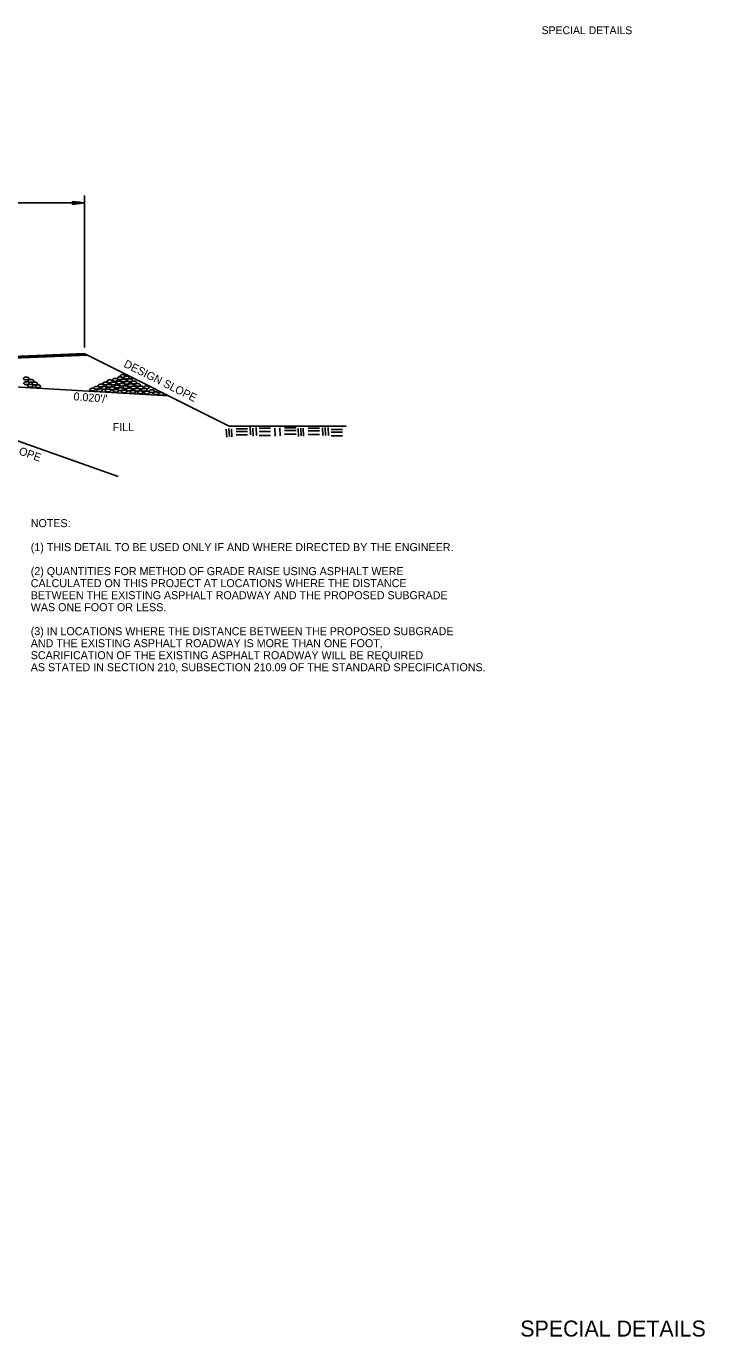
# Model space of a CAD drawing. Extents: x 836 to 5683, y -463 to 1545.
# Drawn here: x 5174 to 5683, y 35 to 1017 of the extents above; entities that cross this region are included whole.
import ezdxf

# ---------------------------------------------------------------- set-up
doc = ezdxf.new("R2010")
doc.units = 0
for name, color, linetype in [('R_Border', 7, 'Continuous'), ('R_Border Prem', 7, 'Continuous'), ('R_Grid', 7, 'Continuous'), ('R_No Plot', 7, 'Continuous')]:
    doc.layers.add(name, color=color, linetype=linetype)

msp = doc.modelspace()

# ---------------------------------------------------------------- linework, layer by layer
at = {"layer": 'R_Grid'}
for p, q in [((4657.04, 884.96), (5217.98, 884.96)), ((5209.15, 886.1), (5217.98, 884.96)), ((5209.15, 883.81), (5209.15, 886.1)), ((5209.15, 885.87), (5210.88, 885.88)), ((5209.15, 885.64), (5212.67, 885.65)), ((5209.15, 885.42), (5214.45, 885.41)), ((5209.15, 885.18), (5216.18, 885.18)), ((5217.98, 884.96), (5209.15, 884.96)), ((5209.15, 883.81), (5217.98, 884.96)), ((5209.15, 884.73), (5216.18, 884.73)), ((5209.15, 884.5), (5214.45, 884.51)), ((5209.16, 884.27), (5212.67, 884.27)), ((5217.98, 776.58), (5217.98, 890.46)), ((5209.15, 884.04), (5210.89, 884.05))]:
    msp.add_line(p, q, dxfattribs=at)
at = {"layer": 'R_No Plot'}
for p, q in [((4654.18, 748.2), (5220.52, 770.79)), ((4654.91, 748.58), (5219.89, 771.11)), ((4655.64, 748.93), (5219.26, 771.42)), ((4656.39, 749.31), (5218.6, 771.74)), ((4657.04, 749.63), (5218, 772.04)), ((5326.58, 717.76), (5217.91, 772.08)), ((5146.72, 748.27), (5281.29, 740.39)), ((5091.21, 733.94), (5243.32, 679.81)), ((5414.15, 717.76), (5326.58, 717.76)), ((5342.3, 717.13), (5342.61, 711.22)), ((5324.36, 715.43), (5324.69, 709.5)), ((5326.39, 715.82), (5326.73, 709.9)), ((5328.17, 715.63), (5328.49, 709.71)), ((5340.36, 715.63), (5331.79, 715.63)), ((5340.36, 713.66), (5331.79, 713.66)), ((5340.36, 711.02), (5331.79, 711.02)), ((5344.3, 716.13), (5344.62, 710.21)), ((5346.83, 716.65), (5347.15, 710.71)), ((5357.53, 716.14), (5348.93, 716.14)), ((5357.53, 713.6), (5348.93, 713.6)), ((5357.53, 710.58), (5348.93, 710.58)), ((5360.7, 716.07), (5361.05, 710.14)), ((5364.51, 716.28), (5364.84, 710.36)), ((5376.7, 716.28), (5368.14, 716.28)), ((5376.7, 714.3), (5368.14, 714.3)), ((5376.7, 711.66), (5368.14, 711.66)), ((5378.24, 715.81), (5378.57, 709.89)), ((5380.29, 716.23), (5380.6, 710.3)), ((5382.05, 716.02), (5382.38, 710.08)), ((5394.24, 716.02), (5385.68, 716.02)), ((5394.24, 714.06), (5385.68, 714.06)), ((5394.24, 711.42), (5385.68, 711.42)), ((5396.41, 716.44), (5396.74, 710.52)), ((5398.53, 716.67), (5398.86, 710.75)), ((5400.78, 716.67), (5401.11, 710.75)), ((5411.53, 715.12), (5402.96, 715.12)), ((5411.53, 713.17), (5402.96, 713.17)), ((5411.53, 710.51), (5402.96, 710.51))]:
    msp.add_line(p, q, dxfattribs=at)
for points in [[(5174.26, 752.35), (5173.52, 752.44), (5172.67, 752.66), (5172.25, 753.09), (5172.18, 753.31), (5172.39, 753.77), (5172.64, 753.98), (5173.11, 754.27), (5173.81, 754.41), (5174.16, 754.41), (5174.71, 754.43), (5175.31, 754.35), (5175.79, 754.08), (5176.23, 753.75), (5176.29, 753.47), (5176.18, 753.06), (5175.82, 752.77), (5175.52, 752.63), (5175.02, 752.48), (5174.71, 752.4), (5174.26, 752.35)], [(5174.56, 748.78), (5173.81, 748.85), (5172.97, 749.1), (5172.55, 749.51), (5172.47, 749.76), (5172.72, 750.2), (5172.92, 750.41), (5173.42, 750.65), (5174.11, 750.84), (5174.47, 750.84), (5175.03, 750.79), (5175.62, 750.75), (5176.11, 750.57), (5176.54, 750.16), (5176.61, 749.92), (5176.47, 749.48), (5176.15, 749.24), (5175.8, 749.08), (5175.31, 748.88), (5175.03, 748.79), (5174.56, 748.78)], [(5177.48, 746.82), (5176.72, 746.9), (5175.85, 747.14), (5175.43, 747.55), (5175.35, 747.81), (5175.57, 748.24), (5175.81, 748.45), (5176.31, 748.72), (5177.01, 748.88), (5177.39, 748.88), (5177.93, 748.84), (5178.53, 748.81), (5178.99, 748.61), (5179.43, 748.21), (5179.48, 747.95), (5179.35, 747.53), (5179.02, 747.28), (5178.69, 747.13), (5178.22, 746.94), (5177.93, 746.83), (5177.48, 746.82)], [(5177.95, 750.6), (5177.21, 750.65), (5176.35, 750.9), (5175.92, 751.3), (5175.86, 751.57), (5176.12, 751.99), (5176.3, 752.21), (5176.82, 752.47), (5177.5, 752.65), (5177.85, 752.65), (5178.41, 752.61), (5179.02, 752.57), (5179.48, 752.36), (5179.93, 751.97), (5180, 751.71), (5179.86, 751.28), (5179.53, 751.04), (5179.2, 750.89), (5178.7, 750.69), (5178.41, 750.6), (5177.95, 750.6)], [(5180.83, 748.59), (5180.09, 748.66), (5179.24, 748.88), (5178.84, 749.31), (5178.76, 749.53), (5178.98, 749.98), (5179.19, 750.19), (5179.69, 750.48), (5180.38, 750.62), (5180.74, 750.62), (5181.29, 750.6), (5181.91, 750.58), (5182.37, 750.34), (5182.81, 749.96), (5182.87, 749.67), (5182.76, 749.29), (5182.43, 749.01), (5182.1, 748.86), (5181.58, 748.68), (5181.29, 748.6), (5180.83, 748.59)], [(5183.21, 746.47), (5182.46, 746.55), (5181.58, 746.8), (5181.13, 747.19), (5181.07, 747.44), (5181.29, 747.89), (5181.54, 748.08), (5182.06, 748.37), (5182.74, 748.54), (5183.1, 748.54), (5183.64, 748.52), (5184.25, 748.44), (5184.72, 748.22), (5185.12, 747.86), (5185.21, 747.57), (5185.07, 747.18), (5184.73, 746.9), (5184.43, 746.77), (5183.95, 746.61), (5183.66, 746.52), (5183.21, 746.47)], [(5227.25, 745.42), (5226.51, 745.46), (5225.69, 745.71), (5225.24, 746.12), (5225.18, 746.37), (5225.41, 746.82), (5225.64, 747.02), (5226.12, 747.29), (5226.8, 747.46), (5227.17, 747.46), (5227.74, 747.43), (5228.36, 747.4), (5228.79, 747.17), (5229.24, 746.8), (5229.31, 746.51), (5229.17, 746.11), (5228.86, 745.85), (5228.5, 745.7), (5228, 745.5), (5227.74, 745.42), (5227.25, 745.42)], [(5230.3, 747.11), (5229.56, 747.19), (5228.72, 747.43), (5228.31, 747.85), (5228.23, 748.08), (5228.44, 748.54), (5228.65, 748.73), (5229.14, 748.98), (5229.85, 749.19), (5230.21, 749.19), (5230.75, 749.14), (5231.37, 749.1), (5231.83, 748.86), (5232.29, 748.51), (5232.35, 748.2), (5232.22, 747.82), (5231.87, 747.55), (5231.57, 747.41), (5231.06, 747.23), (5230.75, 747.12), (5230.3, 747.11)], [(5232.58, 745.25), (5231.84, 745.32), (5231.01, 745.54), (5230.58, 745.97), (5230.51, 746.2), (5230.74, 746.66), (5230.95, 746.84), (5231.44, 747.12), (5232.15, 747.3), (5232.48, 747.3), (5233.05, 747.27), (5233.65, 747.23), (5234.13, 747), (5234.57, 746.63), (5234.64, 746.34), (5234.5, 745.95), (5234.17, 745.68), (5233.84, 745.52), (5233.37, 745.37), (5233.05, 745.26), (5232.58, 745.25)], [(5233.81, 748.68), (5233.06, 748.76), (5232.21, 749), (5231.75, 749.39), (5231.7, 749.65), (5231.9, 750.08), (5232.19, 750.29), (5232.69, 750.6), (5233.38, 750.73), (5233.72, 750.73), (5234.26, 750.7), (5234.88, 750.64), (5235.34, 750.46), (5235.76, 750.04), (5235.81, 749.8), (5235.68, 749.38), (5235.35, 749.13), (5235.05, 748.96), (5234.59, 748.81), (5234.29, 748.73), (5233.81, 748.68)], [(5236.43, 746.88), (5235.68, 746.97), (5234.83, 747.2), (5234.41, 747.61), (5234.35, 747.86), (5234.57, 748.3), (5234.78, 748.52), (5235.29, 748.77), (5235.97, 748.93), (5236.33, 748.93), (5236.89, 748.91), (5237.5, 748.86), (5237.95, 748.66), (5238.4, 748.27), (5238.46, 748.01), (5238.32, 747.58), (5238, 747.35), (5237.66, 747.19), (5237.18, 747), (5236.89, 746.89), (5236.43, 746.88)], [(5236.94, 750.2), (5236.22, 750.28), (5235.35, 750.57), (5234.93, 750.94), (5234.85, 751.2), (5235.09, 751.64), (5235.33, 751.86), (5235.79, 752.11), (5236.48, 752.27), (5236.86, 752.27), (5237.4, 752.3), (5238, 752.18), (5238.49, 751.96), (5238.92, 751.6), (5238.98, 751.32), (5238.87, 750.91), (5238.53, 750.63), (5238.22, 750.52), (5237.69, 750.36), (5237.4, 750.25), (5236.94, 750.2)], [(5238.85, 744.96), (5238.09, 745.05), (5237.21, 745.3), (5236.77, 745.68), (5236.69, 745.95), (5236.93, 746.38), (5237.18, 746.59), (5237.68, 746.87), (5238.36, 747.03), (5238.73, 747.03), (5239.27, 747.01), (5239.89, 746.94), (5240.35, 746.75), (5240.76, 746.35), (5240.84, 746.09), (5240.69, 745.68), (5240.36, 745.42), (5240.05, 745.27), (5239.59, 745.12), (5239.29, 745.01), (5238.85, 744.96)], [(5239.76, 748.49), (5239.03, 748.58), (5238.19, 748.81), (5237.74, 749.23), (5237.66, 749.44), (5237.9, 749.93), (5238.16, 750.13), (5238.6, 750.41), (5239.31, 750.57), (5239.68, 750.57), (5240.23, 750.59), (5240.84, 750.49), (5241.31, 750.25), (5241.74, 749.9), (5241.8, 749.62), (5241.68, 749.22), (5241.35, 748.92), (5241.01, 748.78), (5240.52, 748.64), (5240.23, 748.54), (5239.76, 748.49)], [(5240.98, 751.32), (5240.23, 751.4), (5239.36, 751.66), (5238.92, 752.05), (5238.87, 752.32), (5239.09, 752.75), (5239.33, 752.97), (5239.81, 753.21), (5240.52, 753.38), (5240.88, 753.38), (5241.44, 753.35), (5242.05, 753.31), (5242.49, 753.12), (5242.92, 752.72), (5242.99, 752.46), (5242.84, 752.03), (5242.51, 751.78), (5242.19, 751.65), (5241.73, 751.44), (5241.44, 751.33), (5240.98, 751.32)], [(5242.41, 746.34), (5241.68, 746.41), (5240.83, 746.67), (5240.39, 747.06), (5240.32, 747.3), (5240.54, 747.74), (5240.8, 748), (5241.25, 748.22), (5241.95, 748.38), (5242.31, 748.38), (5242.85, 748.41), (5243.47, 748.3), (5243.94, 748.09), (5244.38, 747.7), (5244.44, 747.46), (5244.32, 747.03), (5243.98, 746.78), (5243.65, 746.63), (5243.16, 746.48), (5242.85, 746.37), (5242.41, 746.34)], [(5243.89, 749.4), (5243.15, 749.49), (5242.27, 749.75), (5241.81, 750.13), (5241.76, 750.4), (5242, 750.82), (5242.24, 751.04), (5242.77, 751.31), (5243.45, 751.47), (5243.79, 751.47), (5244.35, 751.44), (5244.94, 751.37), (5245.43, 751.2), (5245.82, 750.79), (5245.9, 750.55), (5245.76, 750.11), (5245.44, 749.89), (5245.12, 749.71), (5244.66, 749.56), (5244.37, 749.46), (5243.89, 749.4)], [(5244.81, 752.56), (5244.09, 752.65), (5243.21, 752.88), (5242.8, 753.29), (5242.74, 753.54), (5242.96, 753.96), (5243.19, 754.18), (5243.68, 754.45), (5244.37, 754.62), (5244.74, 754.62), (5245.28, 754.57), (5245.9, 754.53), (5246.36, 754.35), (5246.77, 753.94), (5246.84, 753.7), (5246.72, 753.27), (5246.39, 753.03), (5246.07, 752.85), (5245.56, 752.66), (5245.28, 752.58), (5244.81, 752.56)], [(5246.21, 747.68), (5245.49, 747.76), (5244.64, 748.01), (5244.2, 748.41), (5244.15, 748.66), (5244.37, 749.11), (5244.57, 749.31), (5245.08, 749.56), (5245.77, 749.75), (5246.13, 749.75), (5246.68, 749.71), (5247.29, 749.66), (5247.76, 749.43), (5248.21, 749.07), (5248.26, 748.78), (5248.14, 748.38), (5247.81, 748.12), (5247.48, 748), (5246.99, 747.79), (5246.68, 747.69), (5246.21, 747.68)], [(5246.77, 754.19), (5246.04, 754.28), (5245.19, 754.5), (5244.78, 754.93), (5244.71, 755.16), (5244.93, 755.61), (5245.13, 755.81), (5245.63, 756.07), (5246.33, 756.25), (5246.69, 756.25), (5247.25, 756.22), (5247.85, 756.18), (5248.31, 755.95), (5248.77, 755.59), (5248.84, 755.27), (5248.71, 754.91), (5248.37, 754.62), (5248.04, 754.5), (5247.54, 754.32), (5247.25, 754.21), (5246.77, 754.19)], [(5247.4, 750.93), (5246.64, 751.01), (5245.78, 751.23), (5245.34, 751.66), (5245.28, 751.89), (5245.5, 752.35), (5245.75, 752.53), (5246.23, 752.8), (5246.94, 752.99), (5247.3, 752.99), (5247.85, 752.94), (5248.46, 752.91), (5248.9, 752.66), (5249.34, 752.32), (5249.41, 752), (5249.27, 751.64), (5248.93, 751.34), (5248.62, 751.23), (5248.15, 751.04), (5247.85, 750.94), (5247.4, 750.93)], [(5248.75, 747.93), (5249.46, 747.91), (5250.37, 747.59), (5250.78, 747.2), (5250.85, 746.94), (5250.62, 746.51), (5250.38, 746.31), (5249.9, 746.09), (5249.19, 745.9), (5248.83, 745.87), (5248.27, 745.92), (5247.69, 746.02), (5247.22, 746.17), (5246.79, 746.54), (5246.72, 746.8), (5246.85, 747.21), (5247.2, 747.47), (5247.5, 747.69), (5247.98, 747.85), (5248.28, 747.91), (5248.75, 747.93)], [(5249.55, 753.01), (5248.84, 753.1), (5247.95, 753.31), (5247.53, 753.74), (5247.47, 753.96), (5247.69, 754.42), (5247.94, 754.6), (5248.42, 754.88), (5249.11, 755.07), (5249.46, 755.07), (5250.03, 755.01), (5250.63, 754.98), (5251.1, 754.75), (5251.52, 754.39), (5251.6, 754.08), (5251.46, 753.73), (5251.15, 753.43), (5250.79, 753.29), (5250.32, 753.12), (5250.03, 753.03), (5249.55, 753.01)], [(5249.84, 749.07), (5249.1, 749.17), (5248.24, 749.38), (5247.81, 749.81), (5247.74, 750.04), (5247.96, 750.51), (5248.22, 750.67), (5248.71, 750.96), (5249.4, 751.15), (5249.76, 751.15), (5250.3, 751.1), (5250.91, 751.06), (5251.37, 750.84), (5251.81, 750.48), (5251.88, 750.17), (5251.75, 749.8), (5251.4, 749.52), (5251.09, 749.36), (5250.59, 749.22), (5250.3, 749.1), (5249.84, 749.07)], [(5252.18, 751.08), (5251.41, 751.15), (5250.57, 751.35), (5250.11, 751.8), (5250.06, 752.02), (5250.28, 752.48), (5250.54, 752.66), (5251.03, 752.95), (5251.73, 753.13), (5252.07, 753.13), (5252.63, 753.1), (5253.23, 753.06), (5253.7, 752.82), (5254.11, 752.46), (5254.18, 752.17), (5254.05, 751.78), (5253.73, 751.49), (5253.4, 751.34), (5252.92, 751.2), (5252.63, 751.09), (5252.18, 751.08)], [(5252.64, 749.41), (5253.4, 749.34), (5254.26, 749.11), (5254.71, 748.69), (5254.76, 748.44), (5254.55, 748.02), (5254.3, 747.81), (5253.79, 747.53), (5253.11, 747.37), (5252.73, 747.37), (5252.2, 747.41), (5251.59, 747.44), (5251.13, 747.64), (5250.71, 748.04), (5250.64, 748.3), (5250.77, 748.71), (5251.12, 748.96), (5251.41, 749.13), (5251.9, 749.31), (5252.2, 749.39), (5252.64, 749.41)], [(5254.9, 747.64), (5255.65, 747.58), (5256.53, 747.33), (5256.99, 746.9), (5257.05, 746.66), (5256.81, 746.21), (5256.55, 746.03), (5256.04, 745.8), (5255.34, 745.56), (5254.98, 745.56), (5254.43, 745.62), (5253.84, 745.68), (5253.39, 745.88), (5252.98, 746.24), (5252.91, 746.53), (5253.05, 746.92), (5253.34, 747.19), (5253.64, 747.37), (5254.13, 747.55), (5254.44, 747.61), (5254.9, 747.64)], [(5255.06, 751.44), (5255.78, 751.35), (5256.65, 751.15), (5257.11, 750.72), (5257.17, 750.5), (5256.96, 750.03), (5256.7, 749.86), (5256.19, 749.54), (5255.51, 749.38), (5255.15, 749.38), (5254.61, 749.43), (5253.98, 749.47), (5253.52, 749.68), (5253.12, 750.06), (5253.06, 750.36), (5253.2, 750.73), (5253.49, 751.02), (5253.81, 751.18), (5254.3, 751.31), (5254.6, 751.43), (5255.06, 751.44)], [(5257.69, 749.6), (5258.44, 749.53), (5259.3, 749.31), (5259.76, 748.88), (5259.82, 748.66), (5259.59, 748.19), (5259.35, 748.01), (5258.83, 747.7), (5258.17, 747.55), (5257.79, 747.55), (5257.23, 747.58), (5256.6, 747.62), (5256.17, 747.86), (5255.75, 748.21), (5255.69, 748.52), (5255.83, 748.9), (5256.14, 749.19), (5256.45, 749.31), (5256.95, 749.47), (5257.22, 749.59), (5257.69, 749.6)], [(5260.18, 747.7), (5260.91, 747.62), (5261.77, 747.4), (5262.22, 746.99), (5262.29, 746.75), (5262.03, 746.29), (5261.79, 746.11), (5261.31, 745.84), (5260.61, 745.64), (5260.25, 745.64), (5259.7, 745.7), (5259.1, 745.74), (5258.63, 745.95), (5258.21, 746.34), (5258.17, 746.6), (5258.27, 747), (5258.61, 747.27), (5258.92, 747.43), (5259.41, 747.62), (5259.73, 747.69), (5260.18, 747.7)], [(5264.7, 745.8), (5263.97, 745.88), (5263.11, 746.11), (5262.69, 746.52), (5262.62, 746.77), (5262.86, 747.21), (5263.07, 747.41), (5263.57, 747.67), (5264.24, 747.86), (5264.63, 747.86), (5265.17, 747.82), (5265.78, 747.77), (5266.24, 747.55), (5266.68, 747.18), (5266.75, 746.88), (5266.62, 746.5), (5266.3, 746.22), (5265.96, 746.1), (5265.45, 745.91), (5265.17, 745.8), (5264.7, 745.8)], [(5224.03, 744), (5223.3, 744.06), (5222.45, 744.28), (5222.04, 744.71), (5221.96, 744.94), (5222.2, 745.42), (5222.41, 745.6), (5222.9, 745.88), (5223.6, 746.05), (5223.95, 746.05), (5224.51, 746.02), (5225.13, 745.97), (5225.6, 745.75), (5226.01, 745.39), (5226.09, 745.09), (5225.95, 744.7), (5225.65, 744.42), (5225.28, 744.26), (5224.8, 744.11), (5224.51, 744.01), (5224.03, 744)], [(5229.49, 743.57), (5228.73, 743.64), (5227.88, 743.88), (5227.45, 744.28), (5227.38, 744.54), (5227.64, 744.98), (5227.82, 745.2), (5228.36, 745.44), (5229.03, 745.62), (5229.38, 745.62), (5229.94, 745.58), (5230.54, 745.54), (5231.01, 745.34), (5231.46, 744.94), (5231.54, 744.68), (5231.38, 744.25), (5231.06, 744.02), (5230.74, 743.87), (5230.23, 743.67), (5229.94, 743.58), (5229.49, 743.57)], [(5235.69, 743.31), (5234.95, 743.4), (5234.11, 743.62), (5233.68, 744.05), (5233.62, 744.26), (5233.84, 744.74), (5234.06, 744.92), (5234.55, 745.21), (5235.24, 745.39), (5235.6, 745.39), (5236.17, 745.35), (5236.77, 745.3), (5237.23, 745.08), (5237.66, 744.71), (5237.74, 744.41), (5237.62, 744.03), (5237.28, 743.74), (5236.96, 743.62), (5236.45, 743.44), (5236.17, 743.32), (5235.69, 743.31)], [(5241.5, 745.14), (5242.2, 745.12), (5243.09, 744.81), (5243.52, 744.41), (5243.59, 744.17), (5243.37, 743.7), (5243.09, 743.53), (5242.64, 743.29), (5241.91, 743.09), (5241.55, 743.07), (5241.01, 743.11), (5240.42, 743.23), (5239.96, 743.41), (5239.53, 743.74), (5239.47, 744.04), (5239.59, 744.42), (5239.92, 744.7), (5240.23, 744.89), (5240.71, 745.05), (5241.03, 745.12), (5241.5, 745.14)], [(5245.11, 746.44), (5245.84, 746.42), (5246.72, 746.12), (5247.15, 745.71), (5247.21, 745.45), (5246.99, 745.01), (5246.72, 744.81), (5246.25, 744.59), (5245.52, 744.4), (5245.17, 744.36), (5244.64, 744.42), (5244.05, 744.53), (5243.57, 744.71), (5243.15, 745.05), (5243.09, 745.34), (5243.21, 745.73), (5243.55, 745.99), (5243.85, 746.2), (5244.35, 746.35), (5244.65, 746.42), (5245.11, 746.44)], [(5247.81, 744.67), (5248.54, 744.59), (5249.4, 744.29), (5249.83, 743.93), (5249.9, 743.67), (5249.66, 743.24), (5249.41, 743.01), (5248.93, 742.74), (5248.24, 742.58), (5247.88, 742.58), (5247.33, 742.57), (5246.72, 742.66), (5246.25, 742.89), (5245.82, 743.26), (5245.76, 743.52), (5245.9, 743.94), (5246.21, 744.2), (5246.55, 744.35), (5247.05, 744.51), (5247.33, 744.61), (5247.81, 744.67)], [(5251.27, 746.14), (5252, 746.09), (5252.88, 745.83), (5253.33, 745.43), (5253.4, 745.2), (5253.17, 744.74), (5252.92, 744.54), (5252.42, 744.22), (5251.75, 744.11), (5251.37, 744.11), (5250.81, 744.12), (5250.21, 744.18), (5249.76, 744.39), (5249.34, 744.78), (5249.27, 745.05), (5249.41, 745.44), (5249.74, 745.71), (5250.06, 745.87), (5250.52, 746.02), (5250.8, 746.11), (5251.27, 746.14)], [(5254.33, 744.35), (5255.07, 744.25), (5255.93, 744.05), (5256.36, 743.62), (5256.42, 743.38), (5256.18, 742.95), (5255.96, 742.74), (5255.45, 742.49), (5254.76, 742.29), (5254.42, 742.29), (5253.88, 742.32), (5253.26, 742.39), (5252.8, 742.58), (5252.35, 742.97), (5252.29, 743.24), (5252.42, 743.64), (5252.75, 743.91), (5253.09, 744.06), (5253.57, 744.22), (5253.88, 744.32), (5254.33, 744.35)], [(5257.42, 745.97), (5258.17, 745.91), (5259.02, 745.66), (5259.45, 745.26), (5259.51, 745), (5259.3, 744.57), (5259.04, 744.35), (5258.56, 744.11), (5257.86, 743.92), (5257.52, 743.92), (5256.96, 743.97), (5256.36, 744.01), (5255.9, 744.22), (5255.44, 744.59), (5255.39, 744.85), (5255.52, 745.27), (5255.87, 745.52), (5256.18, 745.68), (5256.65, 745.88), (5256.96, 745.97), (5257.42, 745.97)], [(5259.86, 744.06), (5260.61, 744.02), (5261.45, 743.73), (5261.87, 743.33), (5261.94, 743.07), (5261.71, 742.63), (5261.51, 742.45), (5261.01, 742.22), (5260.32, 741.97), (5259.95, 741.97), (5259.41, 742.04), (5258.82, 742.11), (5258.32, 742.29), (5257.87, 742.66), (5257.8, 742.95), (5257.95, 743.34), (5258.27, 743.62), (5258.61, 743.79), (5259.1, 743.99), (5259.41, 744.05), (5259.86, 744.06)], [(5262.76, 745.89), (5263.48, 745.84), (5264.37, 745.56), (5264.78, 745.15), (5264.84, 744.89), (5264.63, 744.45), (5264.42, 744.24), (5263.91, 744.04), (5263.22, 743.82), (5262.86, 743.82), (5262.29, 743.87), (5261.71, 743.96), (5261.23, 744.13), (5260.8, 744.5), (5260.72, 744.79), (5260.87, 745.18), (5261.18, 745.44), (5261.54, 745.61), (5261.99, 745.8), (5262.29, 745.88), (5262.76, 745.89)], [(5264.76, 743.77), (5265.48, 743.75), (5266.36, 743.48), (5266.75, 743.08), (5266.83, 742.86), (5266.61, 742.37), (5266.39, 742.18), (5265.91, 741.92), (5265.2, 741.76), (5264.81, 741.71), (5264.28, 741.78), (5263.69, 741.89), (5263.21, 742.04), (5262.77, 742.41), (5262.7, 742.66), (5262.85, 743.07), (5263.16, 743.37), (5263.49, 743.56), (5263.99, 743.67), (5264.3, 743.75), (5264.76, 743.77)], [(5268.52, 744.91), (5269.25, 744.85), (5270.11, 744.59), (5270.55, 744.22), (5270.61, 744), (5270.38, 743.51), (5270.16, 743.26), (5269.64, 743.04), (5268.97, 742.9), (5268.61, 742.87), (5268.06, 742.87), (5267.43, 742.97), (5267.01, 743.19), (5266.55, 743.53), (5266.48, 743.82), (5266.61, 744.22), (5266.95, 744.52), (5267.27, 744.67), (5267.76, 744.81), (5268.05, 744.85), (5268.52, 744.91)], [(5271.49, 743.37), (5272.22, 743.29), (5273.07, 743.03), (5273.48, 742.63), (5273.55, 742.41), (5273.35, 741.93), (5273.11, 741.71), (5272.61, 741.45), (5271.91, 741.31), (5271.56, 741.31), (5271.01, 741.32), (5270.42, 741.37), (5269.94, 741.61), (5269.49, 741.95), (5269.42, 742.27), (5269.55, 742.65), (5269.89, 742.94), (5270.21, 743.07), (5270.71, 743.23), (5271.03, 743.32), (5271.49, 743.37)], [(5275.47, 740.78), (5274.71, 740.84), (5273.87, 741.08), (5273.44, 741.49), (5273.38, 741.74), (5273.62, 742.21), (5273.82, 742.39), (5274.33, 742.63), (5275.03, 742.85), (5275.39, 742.85), (5275.92, 742.81), (5276.53, 742.75), (5276.99, 742.53), (5277.44, 742.17), (5277.49, 741.89), (5277.38, 741.47), (5277.06, 741.22), (5276.73, 741.06), (5276.22, 740.88), (5275.92, 740.79), (5275.47, 740.78)]]:
    msp.add_spline(points, degree=3, dxfattribs=at)

# ---------------------------------------------------------------- texts
at = {"layer": 'R_Border'}
for s, height, p in [('NOTES:', 6, (5177.77, 641.97)), ('(1) THIS DETAIL TO BE USED ONLY IF AND WHERE DIRECTED BY THE ENGINEER.', 6, (5177.77, 623.97)), ('(2) QUANTITIES FOR METHOD OF GRADE RAISE USING ASPHALT WERE', 6, (5177.77, 605.97)), ('CALCULATED ON THIS PROJECT AT LOCATIONS WHERE THE DISTANCE', 6, (5177.77, 596.97)), ('BETWEEN THE EXISTING ASPHALT ROADWAY AND THE PROPOSED SUBGRADE', 6, (5177.77, 587.97)), ('WAS ONE FOOT OR LESS.', 6, (5177.77, 578.97)), ('(3) IN LOCATIONS WHERE THE DISTANCE BETWEEN THE PROPOSED SUBGRADE', 6, (5177.77, 560.97)), ('AND THE EXISTING ASPHALT ROADWAY IS MORE THAN ONE FOOT,', 6, (5177.77, 551.97)), ('SCARIFICATION OF THE EXISTING ASPHALT ROADWAY WILL BE REQUIRED', 6, (5177.77, 542.97)), ('AS STATED IN SECTION 210, SUBSECTION 210.09 OF THE STANDARD SPECIFICATIONS.', 6, (5177.77, 533.97)), ('SPECIAL DETAILS', 12, (5544.77, 35.29))]:
    msp.add_text(s, height=height, dxfattribs=at).set_placement(p)
at = {"layer": 'R_Border Prem'}
msp.add_text('SPECIAL DETAILS', height=5.862, dxfattribs=at).set_placement((5560.81, 1011.46))
at = {"layer": 'R_No Plot'}
for s, rotation, p in [('DESIGN SLOPE', 333.43495, (5246.98, 762.36)), ("0.020'/'", 355.62317, (5209.66, 737.07)), ('EXISTING SLOPE', 340.41084, (5121.69, 713.23))]:
    msp.add_text(s, height=6, rotation=rotation, dxfattribs=at).set_placement(p)
msp.add_text('FILL', height=6, dxfattribs=at).set_placement((5239.17, 713.97))

doc.saveas('drawing.dxf')
